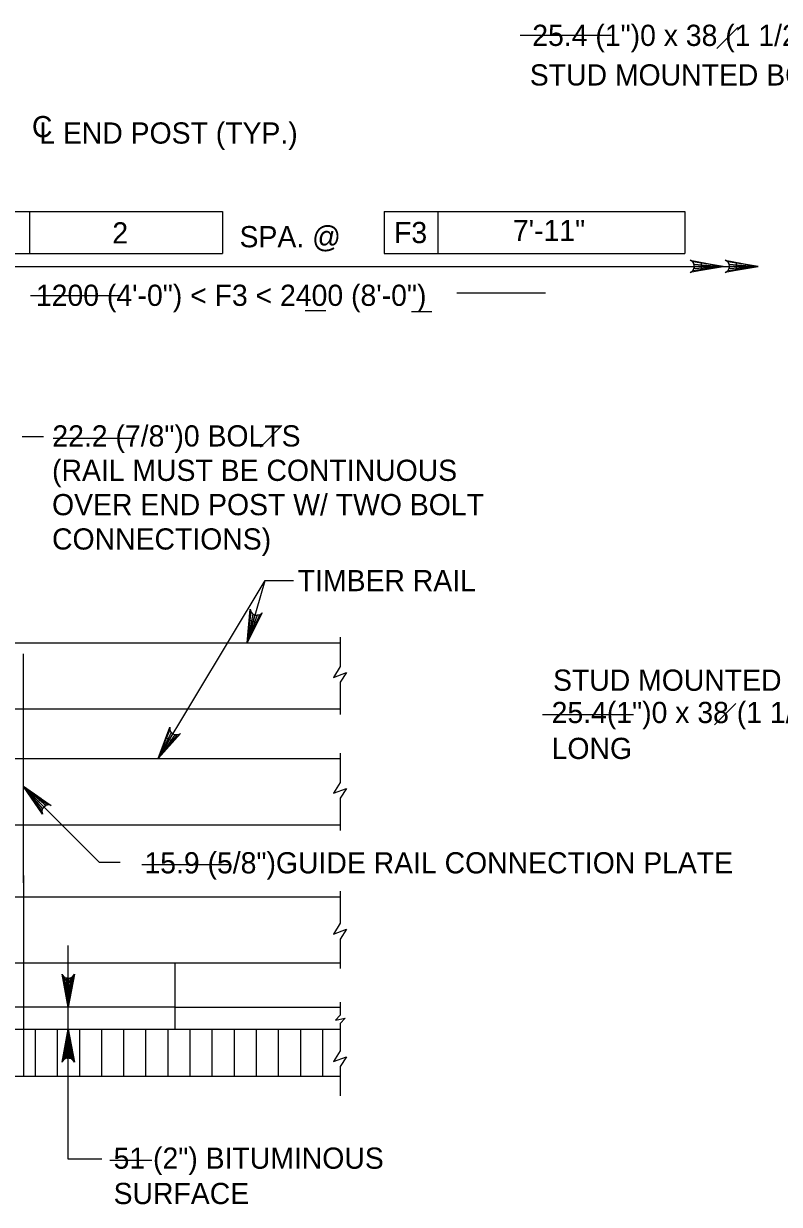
# Model space of a CAD drawing. Extents: x 179 to 454, y -271 to 54.
# Drawn here: x 369.65 to 373.93, y -16.23 to -9.55 of the extents above; entities that cross this region are included whole.
import ezdxf

# ---------------------------------------------------------------- set-up
doc = ezdxf.new("R2010")
doc.units = 0
for name, color, linetype in [('Level 2', 7, 'Continuous'), ('Level 3', 7, 'Continuous'), ('Level 41', 7, 'Continuous'), ('Level 5', 7, 'Continuous')]:
    doc.layers.add(name, color=color, linetype=linetype)

msp = doc.modelspace()

# ---------------------------------------------------------------- linework, layer by layer
at = {"layer": 'Level 2'}
for p, q in [((371.4434, -13.0173), (371.4434, -13.1829)), ((367.8979, -13.0486), (369.9448, -13.0486)), ((369.9448, -13.0486), (371.4434, -13.0486)), ((371.4434, -13.1829), (371.4062, -13.2448)), ((371.4062, -13.2448), (371.4803, -13.217)), ((371.4803, -13.217), (371.4434, -13.2727)), ((371.4434, -13.2727), (371.4434, -13.4548)), ((367.8979, -13.4236), (369.6531, -13.4236)), ((369.6531, -13.4236), (371.4434, -13.4236)), ((371.4434, -13.6736), (371.4434, -13.8392)), ((367.8979, -13.7047), (369.6531, -13.7047)), ((369.6531, -13.7047), (371.4434, -13.7047)), ((371.4434, -13.8392), (371.4062, -13.9011)), ((371.4062, -13.9011), (371.4803, -13.8732)), ((371.4803, -13.8732), (371.4434, -13.9289)), ((371.4434, -13.9289), (371.4434, -14.1111)), ((368.0854, -14.0797), (369.6531, -14.0797)), ((369.6531, -14.0797), (371.4434, -14.0797)), ((369.6531, -14.3656), (369.6531, -14.4861)), ((365.6163, -14.4861), (371.4434, -14.4861)), ((369.6531, -14.4697), (369.6531, -14.5355)), ((369.6531, -14.4861), (369.6531, -15.5017)), ((371.4434, -14.4547), (371.4434, -14.6367)), ((371.4434, -14.6367), (371.4062, -14.6987)), ((371.4062, -14.6987), (371.4803, -14.6708)), ((371.4803, -14.6708), (371.4434, -14.7265)), ((371.4434, -14.7265), (371.4434, -14.8922)), ((365.6163, -14.861), (371.4434, -14.861)), ((370.5075, -14.861), (370.5075, -15.236)), ((371.4434, -15.083), (371.4434, -15.1568)), ((370.5075, -15.111), (371.4434, -15.111)), ((371.4434, -15.1568), (371.4176, -15.1847)), ((371.4176, -15.1847), (371.4722, -15.1734)), ((371.4722, -15.1734), (371.4434, -15.2033)), ((371.4434, -15.2033), (371.4434, -15.236)), ((365.6163, -15.236), (371.4434, -15.236)), ((371.4434, -15.2357), (371.4434, -15.3577)), ((371.4434, -15.236), (371.4434, -15.2444)), ((371.4434, -15.3577), (371.4062, -15.4196)), ((371.4062, -15.4196), (371.4803, -15.3918)), ((371.4803, -15.3918), (371.4434, -15.4474)), ((365.6163, -15.5017), (371.4434, -15.5017)), ((371.4434, -15.4474), (371.4434, -15.6132))]:
    msp.add_line(p, q, dxfattribs=at)
at = {"layer": 'Level 3'}
for p, q in [((373.5739, -9.6862), (373.6931, -9.567)), ((369.3836, -10.6093), (369.686, -10.6093)), ((369.686, -10.6093), (369.686, -10.8455)), ((369.686, -10.6093), (370.7788, -10.6093)), ((370.7788, -10.6093), (370.7788, -10.8455)), ((371.6931, -10.6093), (371.9955, -10.6093)), ((371.6931, -10.6093), (371.6931, -10.8455)), ((371.9955, -10.6093), (371.9955, -10.8455)), ((371.9955, -10.6093), (373.3938, -10.6093)), ((373.3938, -10.6093), (373.3938, -10.8455)), ((369.3836, -10.8455), (370.7788, -10.8455)), ((371.6931, -10.8455), (373.3938, -10.8455)), ((369.2781, -10.9191), (373.8082, -10.9191)), ((371.2465, -11.1684), (371.3629, -11.1684)), ((371.8462, -11.1743), (371.9625, -11.1743)), ((370.9923, -11.9418), (371.1137, -11.8204)), ((369.6448, -11.8824), (369.7648, -11.8824)), ((370.4138, -13.7047), (371.0186, -12.6965)), ((370.9167, -13.0486), (371.0186, -12.6965)), ((371.0186, -12.6965), (371.1436, -12.6965)), ((371.0186, -12.6965), (371.1804, -12.6965)), ((369.6531, -14.4072), (369.6531, -13.1111)), ((373.5602, -13.5137), (373.6815, -13.3923)), ((369.6531, -13.8617), (370.0797, -14.2905)), ((370.0797, -14.2905), (370.1997, -14.2905)), ((369.9054, -15.9711), (369.9054, -14.7624)), ((370.5075, -15.111), (365.3121, -15.111)), ((369.7203, -15.5017), (369.7203, -15.236)), ((369.8453, -15.5017), (369.8453, -15.236)), ((369.9703, -15.5017), (369.9703, -15.236)), ((370.0953, -15.5017), (370.0953, -15.236)), ((370.2202, -15.5017), (370.2202, -15.236)), ((370.3452, -15.5017), (370.3452, -15.236)), ((370.4702, -15.5017), (370.4702, -15.236)), ((370.5952, -15.5017), (370.5952, -15.236)), ((370.7202, -15.5017), (370.7202, -15.236)), ((370.8452, -15.5017), (370.8452, -15.236)), ((370.9702, -15.5017), (370.9702, -15.236)), ((371.0952, -15.5017), (371.0952, -15.236)), ((371.2202, -15.5017), (371.2202, -15.236)), ((371.3452, -15.5017), (371.3452, -15.236)), ((370.0958, -15.9711), (369.9054, -15.9711))]:
    msp.add_line(p, q, dxfattribs=at)
for points in [[(373.4847, -10.8982), (373.4847, -10.9399), (373.6097, -10.9191)], [(373.6832, -10.8982), (373.6832, -10.9399), (373.8082, -10.9191)], [(370.9714, -12.9342), (370.9313, -12.9227), (370.9166, -13.0486)], [(370.496, -13.6083), (370.4602, -13.5869), (370.4138, -13.7047)], [(369.7235, -13.9609), (369.7519, -13.9328), (369.6531, -13.8617)]]:
    msp.add_lwpolyline(points, close=True, dxfattribs=at)
for points in [[(370.9167, -13.0486), (370.9349, -12.8598), (370.9405, -12.8763), (370.9504, -12.8869), (370.9618, -12.8925), (370.9744, -12.8939), (370.9885, -12.8902), (371.0021, -12.8792), (370.9167, -13.0486), (370.9885, -12.8902), (370.9744, -12.8939), (370.9167, -13.0486), (370.9618, -12.8925), (370.9504, -12.8869), (370.9167, -13.0486), (370.9405, -12.8763)], [(370.4138, -13.7047), (370.4797, -13.5269), (370.4809, -13.5443), (370.4878, -13.5572), (370.4974, -13.5654), (370.5093, -13.57), (370.5238, -13.5701), (370.5397, -13.5628), (370.4138, -13.7047), (370.5238, -13.5701), (370.5093, -13.57), (370.4138, -13.7047), (370.4974, -13.5654), (370.4878, -13.5572), (370.4138, -13.7047), (370.4809, -13.5443)], [(369.6531, -13.8617), (369.8093, -13.9692), (369.7922, -13.9661), (369.7781, -13.9697), (369.7677, -13.9769), (369.7603, -13.9872), (369.7568, -14.0013), (369.7598, -14.0185), (369.6531, -13.8617), (369.7568, -14.0013), (369.7603, -13.9872), (369.6531, -13.8617), (369.7677, -13.9769), (369.7781, -13.9697), (369.6531, -13.8617), (369.7922, -13.9661)], [(369.9054, -15.111), (369.8704, -14.9246), (369.8754, -14.9318), (369.8804, -14.939), (369.8866, -14.9427), (369.8929, -14.9464), (369.8991, -14.9474), (369.9054, -14.9485), (369.9116, -14.9474), (369.9179, -14.9464), (369.9241, -14.9427), (369.9304, -14.939), (369.9354, -14.9318), (369.9403, -14.9246), (369.9054, -15.111), (369.9354, -14.9318), (369.9304, -14.939), (369.9054, -15.111), (369.9241, -14.9427), (369.9179, -14.9464), (369.9054, -15.111), (369.9116, -14.9474), (369.9054, -14.9485), (369.9054, -15.111), (369.8991, -14.9474), (369.8929, -14.9464), (369.9054, -15.111), (369.8866, -14.9427), (369.8804, -14.939), (369.9054, -15.111), (369.8754, -14.9318)], [(369.9054, -15.236), (369.9403, -15.4224), (369.9354, -15.4152), (369.9304, -15.408), (369.9241, -15.4043), (369.9179, -15.4006), (369.9116, -15.3996), (369.9054, -15.3985), (369.8991, -15.3996), (369.8929, -15.4006), (369.8866, -15.4043), (369.8804, -15.408), (369.8754, -15.4152), (369.8704, -15.4224), (369.9054, -15.236), (369.8754, -15.4152), (369.8804, -15.408), (369.9054, -15.236), (369.8866, -15.4043), (369.8929, -15.4006), (369.9054, -15.236), (369.8991, -15.3996), (369.9054, -15.3985), (369.9054, -15.236), (369.9116, -15.3996), (369.9179, -15.4006), (369.9054, -15.236), (369.9241, -15.4043), (369.9304, -15.408), (369.9054, -15.236), (369.9354, -15.4152)]]:
    msp.add_lwpolyline(points, dxfattribs=at)
at = {"layer": 'Level 41'}
for p, q in [((372.4623, -9.6102), (372.9779, -9.6102)), ((369.6924, -11.0834), (370.194, -11.0834)), ((372.1029, -11.0695), (372.6045, -11.0695)), ((369.8203, -11.8917), (370.2801, -11.8917)), ((372.5875, -13.4543), (373.103, -13.4543)), ((370.3219, -14.3039), (370.8235, -14.3039)), ((370.1408, -15.977), (370.3777, -15.977))]:
    msp.add_line(p, q, dxfattribs=at)
at = {"layer": 'Level 5'}
for points in [[(373.6097, -10.9191), (373.4232, -10.954), (373.4376, -10.9441), (373.445, -10.9316), (373.4472, -10.9191), (373.445, -10.9066), (373.4376, -10.8941), (373.4232, -10.8842), (373.6097, -10.9191), (373.4376, -10.8941), (373.445, -10.9066), (373.6097, -10.9191), (373.4472, -10.9191), (373.445, -10.9316), (373.6097, -10.9191), (373.4376, -10.9441)], [(373.8082, -10.9191), (373.6218, -10.954), (373.6362, -10.9441), (373.6436, -10.9316), (373.6457, -10.9191), (373.6436, -10.9066), (373.6362, -10.8941), (373.6218, -10.8842), (373.8082, -10.9191), (373.6362, -10.8941), (373.6436, -10.9066), (373.8082, -10.9191), (373.6457, -10.9191), (373.6436, -10.9316), (373.8082, -10.9191), (373.6362, -10.9441)]]:
    msp.add_lwpolyline(points, dxfattribs=at)

# ---------------------------------------------------------------- texts
at = {"layer": 'Level 3'}
for s, p in [('25.4 (1")0 x 38 (1 1/2")LONG', (372.5302, -9.6717)), ('STUD MOUNTED BOLTS', (372.5163, -9.8957)), ('C', (369.7001, -10.1883)), ('L END POST (TYP.)', (369.7412, -10.2244)), ('SPA. @', (370.8745, -10.8111)), ('1200 (4\'-0") < F3 < 2400 (8\'-0")', (369.7226, -11.1427)), ('22.2 (7/8")0 BOLTS', (369.8157, -11.9385)), ('(RAIL MUST BE CONTINUOUS', (369.8139, -12.1332)), ('OVER END POST W/ TWO BOLT', (369.8139, -12.3274)), ('CONNECTIONS)', (369.8139, -12.5217)), ('TIMBER RAIL', (371.2038, -12.7573)), ('STUD MOUNTED BOLTS', (372.6477, -13.3208)), ('25.4(1")0 x 38 (1 1/2")', (372.6399, -13.5036)), ('LONG', (372.6399, -13.7069)), ('15.9 (5/8")GUIDE RAIL CONNECTION PLATE', (370.3365, -14.3544)), ('51 (2") BITUMINOUS', (370.162, -16.0257)), ('SURFACE', (370.162, -16.2257))]:
    msp.add_text(s, height=0.12, dxfattribs=at).set_placement(p)
msp.add_text('F3', height=0.12, rotation=359.93823, dxfattribs=at).set_placement((371.7482, -10.7874))
at = {"layer": 'Level 41'}
for s, p in [('2', (370.1547, -10.7896)), ('7\'-11"', (372.4207, -10.776))]:
    msp.add_text(s, height=0.12, dxfattribs=at).set_placement(p)

doc.saveas('drawing.dxf')
